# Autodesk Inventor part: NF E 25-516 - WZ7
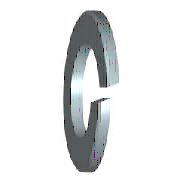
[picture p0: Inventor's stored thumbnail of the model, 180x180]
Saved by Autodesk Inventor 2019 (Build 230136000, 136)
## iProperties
Created: 2018-01
Part Number: NF E 25-516 - WZ7
Material: Acier, doux
Description: Rondelles élastiques à ressort unique, capacité faible
Document SubType Name: Modeling
Standard: NF E 25-516
Designer: Thier
Standards Organization: AFNOR
Language: fr-FR
Size Designation: WZ7
Categories: <MemberInstance><Categories><Category DisplayName="Visserie" InternalName="e4da775c-781d-43d5-af7c-5136215cf5a6" Mnemonic="FSTN"><Category DisplayName="Rondelle
Density: 7.85 g/cm^3
Appearance: Semi-poli
IsCustomPart: 0
Author: Thier
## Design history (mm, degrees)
sketch "Esquisse1"
  geometry: C1 r 5.7 at (0, 0); C2 r 3.75 at (0, 0); 1 further point
  constraints: 2 centre point, 2 coincident
  dimensions: "d0" = 7.5 diameter of C2 (= SD1); "d1" = 11.4 diameter of C1 (= SD2)
extrude "Corps" new body sketch "Esquisse1" distance "d2" = 1.2 (= SD); taper "d3" = 0 deg
sketch "Esquisse2"
  geometry: L1 (0, -3.75)-(0, 3.75) reference; L2 (1.2, 5.7)-(1.2, -5.7) reference; L3 (-1.2, 0)-(7.2, 0) reference; L4 (0, -0.24)-(1.2, 0.453); L5 (0, 0.24)-(1.2, 0.933)
  constraints: 4 end point, 4 point on line, 1 parallel
  dimensions: "d4" = 0.24 distance from line of L3 L4.start (= 0.2 x SD); "d5" = 0.24 distance from line of L3 L5.start (= 0.2 x SD); "d6" = 60 deg angle of L2 L4 (= FAWI)
extrude "Coupe" cut sketch "Esquisse2" stored distance "d7" = 1.2 (= SD); taper "d8" = 0 deg
workaxis "Work Axis1"
workplane "Work Plane1"
body "Solid1"
other parameters: "SD1" = 7.5 [user parameter; used in 1 equation term], "SD2" = 11.4 [user parameter; used in 1 equation term], "SD" = 1.2 [user parameter; used in 4 equation terms], "FAWI" = 60 deg [user parameter; used in 1 equation term], "d9" = 0, "d10" = 0, "d11" = 0, "d12" = 0, "NND" = 7 [user parameter]
